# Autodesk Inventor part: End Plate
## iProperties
Created: 2010-08
Part Number: End Plate
Material: Default
Document SubType Name: Modeling
Designer: Paul Munford
Density: 1 g/cm^3
Author: Paul Munford
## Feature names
1. TaggingFeature2
